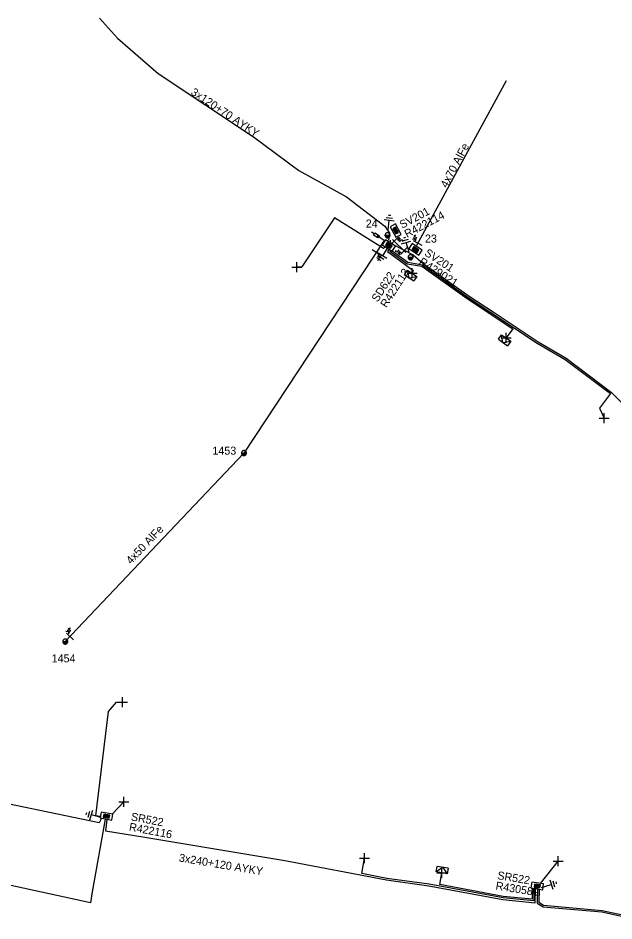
# Model space of a CAD drawing. Extents: x -540247 to -537390, y -1183887 to -1180355.
# Drawn here: x -537931.4 to -537857, y -1180517.1 to -1180404.3 of the extents above; entities that cross this region are included whole.
import ezdxf

# ---------------------------------------------------------------- set-up
doc = ezdxf.new("R2010")
doc.units = 0
for name, color, linetype in [('Vrstva 1', 7, 'Continuous'), ('Vrstva 13', 7, 'Continuous'), ('Vrstva 14', 7, 'Continuous'), ('Vrstva 15', 7, 'Continuous'), ('Vrstva 16', 7, 'Continuous'), ('Vrstva 18', 7, 'Continuous'), ('Vrstva 2', 7, 'Continuous'), ('Vrstva 28', 7, 'Continuous'), ('Vrstva 29', 7, 'Continuous'), ('Vrstva 30', 7, 'Continuous'), ('Vrstva 31', 7, 'Continuous'), ('Vrstva 34', 7, 'Continuous'), ('Vrstva 5', 7, 'Continuous'), ('Vrstva 52', 7, 'Continuous'), ('Vrstva 59', 7, 'Continuous'), ('Vrstva 6', 7, 'Continuous'), ('Vrstva 8', 7, 'Continuous'), ('Vrstva 9', 7, 'Continuous')]:
    doc.layers.add(name, color=color, linetype=linetype)

# ---------------------------------------------------------------- blocks, each defined once
blk = doc.blocks.new('NN440')
at = {"layer": 'Vrstva 2'}
for points in [[(0.63, 0), (0.63, 0.06), (0.62, 0.13), (0.6, 0.19), (0.58, 0.25), (0.55, 0.31), (0.51, 0.37), (0.47, 0.42), (0.42, 0.46), (0.37, 0.51), (0.32, 0.54), (0.26, 0.57), (0.2, 0.59), (0.13, 0.61), (0.07, 0.62), (0, 0.63), (-0.06, 0.62), (-0.13, 0.61), (-0.19, 0.59), (-0.26, 0.57), (-0.31, 0.54), (-0.37, 0.51), (-0.42, 0.46), (-0.47, 0.42), (-0.51, 0.37), (-0.54, 0.31), (-0.57, 0.25), (-0.6, 0.19), (-0.62, 0.13), (-0.63, 0.06), (-0.63, 0), (-0.63, -0.07), (-0.62, -0.14), (-0.6, -0.2), (-0.57, -0.26), (-0.54, -0.32), (-0.51, -0.37), (-0.47, -0.43), (-0.42, -0.47), (-0.37, -0.51), (-0.31, -0.55), (-0.26, -0.58), (-0.19, -0.6), (-0.13, -0.62), (-0.06, -0.63), (0, -0.63), (0.07, -0.63), (0.13, -0.62), (0.2, -0.6), (0.26, -0.58), (0.32, -0.55), (0.37, -0.51), (0.42, -0.47), (0.47, -0.43), (0.51, -0.37), (0.55, -0.32), (0.58, -0.26), (0.6, -0.2), (0.62, -0.14), (0.63, -0.07), (0.63, 0)], [(-0.63, 0), (0.63, 0)], [(-0.6, -0.18), (0.57, -0.18)], [(-0.51, -0.32), (0.5, -0.32)], [(-0.37, -0.47), (0.35, -0.47)]]:
    blk.add_lwpolyline(points, dxfattribs=at)
blk = doc.blocks.new('NN840')
at = {"layer": 'Vrstva 15'}
for points in [[(0, 0.62), (0, -0.63)], [(-0.75, -0.71), (-0.75, -0.66)], [(-0.73, -0.76), (-0.75, -0.71)], [(-0.66, -0.8), (-0.73, -0.76)], [(-0.63, -0.8), (-0.66, -0.8)], [(-0.56, -0.76), (-0.63, -0.8)], [(-0.54, -0.71), (-0.56, -0.76)], [(-0.54, -0.38), (-0.54, -0.71)], [(-0.33, -0.38), (-0.33, -0.8)], [(-0.33, -0.64), (-0.13, -0.38)], [(-0.26, -0.56), (-0.09, -0.8)]]:
    blk.add_lwpolyline(points, dxfattribs=at)
blk = doc.blocks.new('NN800')
at = {"layer": 'Vrstva 1'}
for points in [[(-0.44, 0.44), (0.44, -0.44)], [(-0.44, -0.44), (0.44, 0.44)]]:
    blk.add_lwpolyline(points, dxfattribs=at)
blk = doc.blocks.new('NN820')
at = {"layer": 'Vrstva 13'}
for points in [[(0, 0), (0, -1.05)], [(-0.16, -0.81), (0.16, -0.81)], [(-0.16, -1.47), (-0.16, -0.81)], [(0, -1.05), (-0.06, -0.93)], [(0, -1.05), (0.06, -0.93)], [(0.16, -0.81), (0.16, -1.47)], [(0.16, -1.47), (-0.16, -1.47)], [(0, -1.47), (0, -1.87)]]:
    blk.add_lwpolyline(points, dxfattribs=at)
blk = doc.blocks.new('NN620')
at = {"layer": 'Vrstva 8'}
for points in [[(0.75, 0), (-0.75, 0)], [(-0.75, 0), (-0.75, -0.75)], [(0.75, -0.75), (0.75, 0)], [(-0.75, -0.75), (0.75, -0.75)], [(0.37, -0.18), (-0.38, -0.18)], [(-0.38, -0.18), (-0.38, -0.56)], [(-0.38, -0.56), (0.37, -0.56)], [(0.32, -0.23), (-0.33, -0.23)], [(-0.33, -0.23), (-0.33, -0.51)], [(-0.33, -0.51), (0.32, -0.51)], [(0.27, -0.27), (-0.28, -0.27)], [(-0.28, -0.27), (-0.28, -0.46)], [(-0.28, -0.46), (0.27, -0.46)], [(0.23, -0.32), (-0.23, -0.32)], [(-0.23, -0.32), (-0.23, -0.42)], [(-0.23, -0.42), (0.23, -0.42)], [(-0.19, -0.37), (0.19, -0.37)], [(0.23, -0.42), (0.23, -0.32)], [(0.27, -0.46), (0.27, -0.27)], [(0.32, -0.51), (0.32, -0.23)], [(0.37, -0.56), (0.37, -0.18)]]:
    blk.add_lwpolyline(points, dxfattribs=at)
blk = doc.blocks.new('NN630')
at = {"layer": 'Vrstva 9'}
for points in [[(0, -0.7), (-0.7, 0)], [(-0.7, -0.7), (-0.7, 0), (0.7, 0), (0.7, -0.7)], [(-0.7, -0.7), (0.7, -0.7)], [(0, -0.7), (0.7, 0)]]:
    blk.add_lwpolyline(points, dxfattribs=at)
blk = doc.blocks.new('NN810')
at = {"layer": 'Vrstva 14'}
for points in [[(0, -0.64), (0, -1.89)], [(0.63, -1.89), (-0.62, -1.89)], [(0.39, -2.2), (-0.4, -2.2)], [(0, -2.52), (-0.12, -2.52)], [(0.14, -2.52), (0, -2.52)]]:
    blk.add_lwpolyline(points, dxfattribs=at)

msp = doc.modelspace()

# ---------------------------------------------------------------- linework, layer by layer
at = {"layer": 'Vrstva 1'}
for points in [[(-537870.48, -1180412.17), (-537881.64, -1180432.73)], [(-537885.71, -1180432.12), (-537903.21, -1180458.68), (-537925.53, -1180482.23)], [(-537882.98, -1180433.63), (-537884.64, -1180432.01)]]:
    msp.add_lwpolyline(points, dxfattribs=at)
at = {"layer": 'Vrstva 5'}
for points in [[(-537921.25, -1180404.34), (-537919.01, -1180406.85), (-537913.93, -1180411.26), (-537902, -1180419.18), (-537896.36, -1180423.37), (-537890.41, -1180426.66), (-537885.63, -1180430.34), (-537885.04, -1180431.2), (-537885.17, -1180432.07)], [(-537884.86, -1180432.45), (-537884.89, -1180432.07)], [(-537884.59, -1180432.61), (-537882.08, -1180433.9), (-537880.81, -1180434.99), (-537875.1, -1180439.06), (-537872.09, -1180441.05), (-537866.46, -1180444.78), (-537862.96, -1180446.83), (-537857.29, -1180451.1), (-537852.89, -1180455.49), (-537847.58, -1180461.71), (-537842.1, -1180467.52), (-537838.1, -1180472.04), (-537833.53, -1180476.8), (-537829.32, -1180481.34), (-537827.56, -1180486.21), (-537827.49, -1180486.95), (-537827.36, -1180486.93)], [(-537920.56, -1180504.4), (-537922.18, -1180513.5), (-537922.39, -1180514.88), (-537947.28, -1180509.47), (-537968.09, -1180505.09), (-537988.44, -1180499.35), (-537996.47, -1180497.39), (-538029.52, -1180488.84), (-538052, -1180479.18), (-538051.68, -1180477.71), (-538049.11, -1180472.13), (-538048.48, -1180471.68), (-538047.8, -1180470.31)], [(-537866.54, -1180513.18), (-537866.58, -1180514.91), (-537865.85, -1180515.36), (-537858.5, -1180516.01), (-537853.98, -1180517), (-537849.45, -1180517.13), (-537844.07, -1180516.16), (-537839.96, -1180515.78), (-537835.96, -1180515.9), (-537825.48, -1180515.88), (-537824.36, -1180515.37), (-537824.1, -1180514.31), (-537824.95, -1180510.27), (-537825.63, -1180503.87), (-537825.56, -1180502.07), (-537826.01, -1180499.69), (-537826.76, -1180494.17), (-537827.06, -1180489.39), (-537827.53, -1180487.76), (-537827.27, -1180487.69)], [(-537920.33, -1180504.44), (-537920.51, -1180505.86), (-537915.6, -1180506.68), (-537898.11, -1180509.6), (-537885.4, -1180512.01), (-537880.11, -1180512.74), (-537870.88, -1180514.46), (-537866.83, -1180514.85), (-537866.78, -1180513.14)]]:
    msp.add_lwpolyline(points, dxfattribs=at)
at = {"layer": 'Vrstva 52'}
for points in [[(-537885.58, -1180432.91), (-537885.77, -1180433.14), (-537891.91, -1180429.31), (-537896, -1180435.42), (-537896.62, -1180435.44)], [(-537885.07, -1180433.21), (-537885.27, -1180433.5), (-537882.92, -1180435.23), (-537882.09, -1180435.86), (-537882.19, -1180436.21)], [(-537884.91, -1180433.32), (-537885, -1180433.45), (-537882.84, -1180435.04), (-537881.01, -1180435.34), (-537875.33, -1180439.39), (-537869.64, -1180443.15), (-537870.46, -1180444.3)], [(-537884.68, -1180433.43), (-537882.76, -1180434.85), (-537880.93, -1180435.15), (-537875.21, -1180439.23), (-537866.57, -1180444.95), (-537863.07, -1180447), (-537857.42, -1180451.25), (-537858.79, -1180453.08), (-537858.23, -1180454.32)], [(-537921.15, -1180504.07), (-537921.72, -1180503.99), (-537920.13, -1180490.98), (-537919.12, -1180489.8), (-537918.38, -1180489.8)], [(-537920.99, -1180504.29), (-537921.28, -1180504.86), (-537934.95, -1180502.04), (-537935.03, -1180501.72)], [(-537866.99, -1180513.07), (-537867.02, -1180514.63), (-537870.85, -1180514.26), (-537880.08, -1180512.54), (-537885.37, -1180511.81), (-537888.49, -1180511.21), (-537888.16, -1180509.29)], [(-537867.19, -1180513.03), (-537867.21, -1180514.41), (-537870.82, -1180514.06), (-537878.75, -1180512.59), (-537878.5, -1180511.13)], [(-537866.33, -1180513.18), (-537866.37, -1180514.8), (-537865.79, -1180515.17), (-537858.47, -1180515.81), (-537853.96, -1180516.8), (-537849.46, -1180516.93), (-537844.1, -1180515.96), (-537839.97, -1180515.58), (-537840.24, -1180512.61), (-537839.95, -1180512.41)]]:
    msp.add_lwpolyline(points, dxfattribs=at)
at = {"layer": 'Vrstva 59'}
for points in [[(-537919.66, -1180503.78), (-537918.2, -1180502.24)], [(-537866.18, -1180512.47), (-537863.95, -1180509.68)]]:
    msp.add_lwpolyline(points, dxfattribs=at)

# ---------------------------------------------------------------- block references
at = {"layer": 'Vrstva 13', "xscale": 0.5, "yscale": 0.5}
for p in [(-537885.28, -1180431.47), (-537882.4, -1180434.21), (-537903.21, -1180458.68), (-537925.53, -1180482.23)]:
    msp.add_blockref('NN440', p, dxfattribs=at)
at = {"layer": 'Vrstva 15'}
for p, rotation in [((-537885.28, -1180431.47), 173.72611106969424), ((-537882.41, -1180434.18), -163.60600554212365), ((-537884.92, -1180432.43), -31.51448884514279), ((-537920.45, -1180504.4), -105.75675561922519), ((-537866.64, -1180513.13), 106.88051946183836)]:
    msp.add_blockref('NN810', p, dxfattribs=dict(at, rotation=rotation))
at = {"layer": 'Vrstva 16', "rotation": -123.35733882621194}
msp.add_blockref('NN820', (-537885.71, -1180432.12), dxfattribs=at)
at = {"layer": 'Vrstva 18'}
for p, rotation in [((-537884.45, -1180432.19), 135.71725324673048), ((-537881.5, -1180432.47), -118.50124328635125), ((-537883.2, -1180433.41), -44.28274670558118), ((-537886.67, -1180433.57), 56.642660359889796), ((-537924.93, -1180481.6), -133.47525278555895)]:
    msp.add_blockref('NN840', p, dxfattribs=dict(at, rotation=rotation))
at = {"layer": 'Vrstva 28'}
for p, rotation in [((-537884.59, -1180431.06), 117.97499995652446), ((-537884.92, -1180432.43), -32.6446361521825), ((-537882, -1180433.55), 147.00800007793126), ((-537920.45, -1180504.4), 169.322161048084), ((-537866.64, -1180513.13), 170.6486499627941)]:
    msp.add_blockref('NN620', p, dxfattribs=dict(at, rotation=rotation))
at = {"layer": 'Vrstva 31'}
for p, rotation in [((-537882.19, -1180436.21), -34.28804455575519), ((-537870.46, -1180444.3), -35.16547768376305), ((-537878.5, -1180511.13), 170.60702785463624)]:
    msp.add_blockref('NN630', p, dxfattribs=dict(at, rotation=rotation))
at = {"layer": 'Vrstva 34'}
for p, rotation in [((-537896.62, -1180435.44), 45), ((-537882.19, -1180436.21), 45), ((-537870.46, -1180444.3), 45), ((-537858.23, -1180454.32), 45), ((-537918.38, -1180489.8), 45), ((-537918.2, -1180502.24), 45), ((-537888.16, -1180509.29), 45), ((-537863.95, -1180509.68), 44.99999995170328), ((-537878.5, -1180511.13), 45)]:
    msp.add_blockref('NN800', p, dxfattribs=dict(at, rotation=rotation))

# ---------------------------------------------------------------- texts
at = {"layer": 'Vrstva 14'}
for s, p in [('24', (-537887.99, -1180430.51)), ('23', (-537880.6, -1180432.38)), ('1453', (-537907.15, -1180458.88)), ('1454', (-537927.23, -1180484.83))]:
    msp.add_text(s, height=1, dxfattribs=at).set_placement(p)
at = {"layer": 'Vrstva 2'}
for s, rotation, p in [('4x70 AlFe', 62.107, (-537877.86, -1180425.62)), ('4x50 AlFe', 46.525, (-537917.32, -1180472.64))]:
    msp.add_text(s, height=1, rotation=rotation, dxfattribs=at).set_placement(p)
at = {"layer": 'Vrstva 29'}
for s, rotation, p in [('R422114', 27.975, (-537882.84, -1180431.82)), ('R429021', 327.008, (-537881.45, -1180435.01)), ('R422113', 57.355, (-537885.41, -1180440.59)), ('R422116', 349.322, (-537917.62, -1180505.83)), ('R430589', 350.649, (-537871.83, -1180513.19))]:
    msp.add_text(s, height=1, rotation=rotation, dxfattribs=at).set_placement(p)
at = {"layer": 'Vrstva 30'}
for s, rotation, p in [('SV201', 27.975, (-537883.45, -1180430.67)), ('SV201', 327.008, (-537880.75, -1180433.92)), ('SD622', 57.355, (-537886.51, -1180439.89)), ('SR522', 349.322, (-537917.38, -1180504.56)), ('SR522', 350.649, (-537871.61, -1180511.9))]:
    msp.add_text(s, height=1, rotation=rotation, dxfattribs=at).set_placement(p)
at = {"layer": 'Vrstva 6'}
for s, rotation, p in [('3x120+70 AYKY', 326.421, (-537909.94, -1180413.82)), ('3x240+120 AYKY', 350.522, (-537911.38, -1180509.69))]:
    msp.add_text(s, height=1, rotation=rotation, dxfattribs=at).set_placement(p)

doc.saveas('drawing.dxf')
